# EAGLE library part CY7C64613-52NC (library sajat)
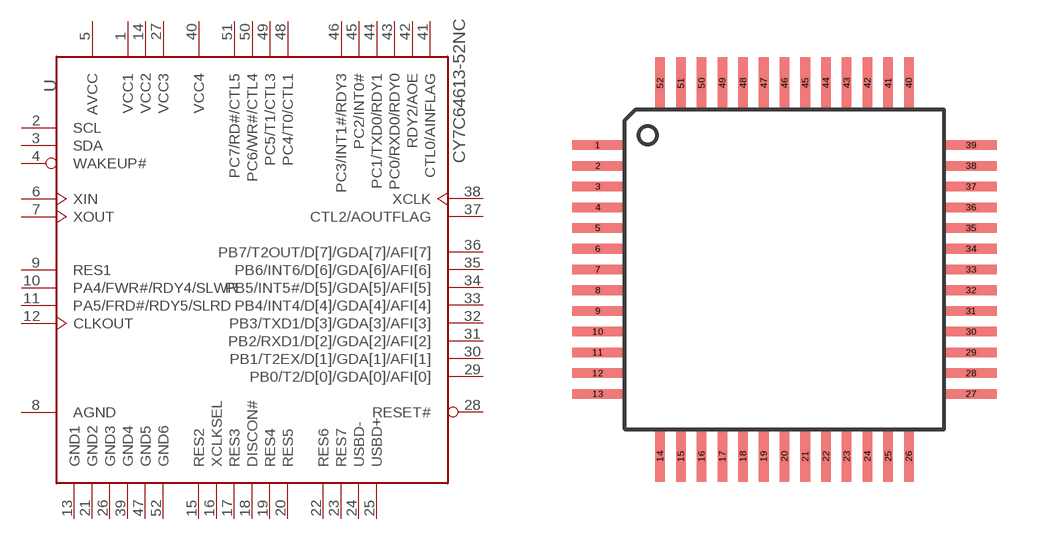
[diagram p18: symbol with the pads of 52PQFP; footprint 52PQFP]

Designator prefix -

## CY7C64613-52NC  [52PQFP]
1  VCC1  pwr
2  SCL
3  SDA
4  WAKEUP#
5  AVCC  pwr
6  XIN
7  XOUT
8  AGND  sup
9  RES1
10  PA4/FWR#/RDY4/SLWR
11  PA5/FRD#/RDY5/SLRD
12  CLKOUT
13  GND1  sup
14  VCC2  pwr
15  RES2
16  XCLKSEL
17  RES3
18  DISCON#
19  RES4
20  RES5
21  GND2  sup
22  RES6
23  RES7
24  USBD-
25  USBD+
26  GND3  sup
27  VCC3  pwr
28  RESET#  in
29  PB0/T2/D[0]/GDA[0]/AFI[0]
30  PB1/T2EX/D[1]/GDA[1]/AFI[1]
31  PB2/RXD1/D[2]/GDA[2]/AFI[2]
32  PB3/TXD1/D[3]/GDA[3]/AFI[3]
33  PB4/INT4/D[4]/GDA[4]/AFI[4]
34  PB5/INT5#/D[5]/GDA[5]/AFI[5]
35  PB6/INT6/D[6]/GDA[6]/AFI[6]
36  PB7/T2OUT/D[7]/GDA[7]/AFI[7]
37  CTL2/AOUTFLAG
38  XCLK
39  GND4  sup
40  VCC4  pwr
41  CTL0/AINFLAG
42  RDY2/AOE
43  PC0/RXD0/RDY0
44  PC1/TXD0/RDY1
45  PC2/INT0#
46  PC3/INT1#/RDY3
47  GND5  sup
48  PC4/T0/CTL1
49  PC5/T1/CTL3
50  PC6/WR#/CTL4
51  PC7/RD#/CTL5
52  GND6  sup

## Footprint 52PQFP (pad centres in mm)
smd 1.6 x 0.3: 1 -5.85,3.9; 2 -5.85,3.25; 3 -5.85,2.6; 4 -5.85,1.95; 5 -5.85,1.3; 6 -5.85,0.65; 7 -5.85,0; 8 -5.85,-0.65; 9 -5.85,-1.3; 10 -5.85,-1.95; 11 -5.85,-2.6; 12 -5.85,-3.25; 13 -5.85,-3.9; 27 5.85,-3.9; 28 5.85,-3.25; 29 5.85,-2.6; 30 5.85,-1.95; 31 5.85,-1.3; 32 5.85,-0.65; 33 5.85,0; 34 5.85,0.65; 35 5.85,1.3; 36 5.85,1.95; 37 5.85,2.6; 38 5.85,3.25; 39 5.85,3.9
smd 0.3 x 1.6: 14 -3.9,-5.85; 15 -3.25,-5.85; 16 -2.6,-5.85; 17 -1.95,-5.85; 18 -1.3,-5.85; 19 -0.65,-5.85; 20 0,-5.85; 21 0.65,-5.85; 22 1.3,-5.85; 23 1.95,-5.85; 24 2.6,-5.85; 25 3.25,-5.85; 26 3.9,-5.85; 40 3.9,5.85; 41 3.25,5.85; 42 2.6,5.85; 43 1.95,5.85; 44 1.3,5.85; 45 0.65,5.85; 46 0,5.85; 47 -0.65,5.85; 48 -1.3,5.85; 49 -1.95,5.85; 50 -2.6,5.85; 51 -3.25,5.85; 52 -3.9,5.85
